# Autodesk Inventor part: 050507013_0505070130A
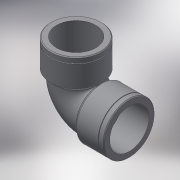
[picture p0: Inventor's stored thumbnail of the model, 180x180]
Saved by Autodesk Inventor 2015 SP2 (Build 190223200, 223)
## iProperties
Created: 2017-05
Part Number: 050507013_0505070130A
Material: Generic
Description: PLASSON THREADED ELBOW 1.1/4"-1.1/4"
Document SubType Name: Modeling
Designer: KIM
Density: 1 g/cm^3
Appearance: Default
Author: KIM
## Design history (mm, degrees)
derived "050507.ipt"
feature "Solid1::050507.ipt"
tag "TaggingFeature1"
body "Solid1"
other parameters: "d0" = 48, "d2" = 0.5, "d3" = 0.5, "d4" = 50.6376, "d5" = 38.952, "d6" = 25, "d7" = 135 deg, "d8" = 29, "d9" = 4.83333, "d19" = 0.77904, "d27" = 25, "d30" = 35.0568, "d31" = 42.8472, "d33" = 90 deg, "d35" = 90 deg, "d36" = 90 deg, "d37" = 1.9476, "Rp_" = 38.952, "A_" = 48, "l_2" = 25
